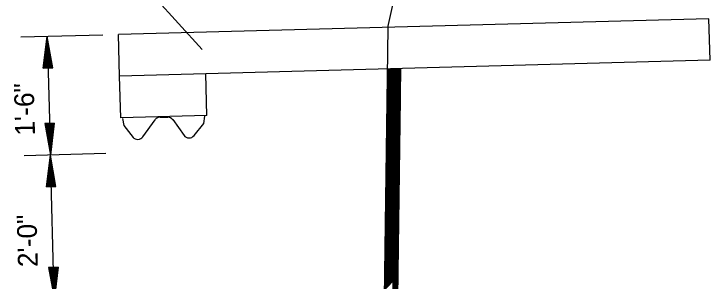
# Model space of a CAD drawing. Extents: x 1929624 to 1936506, y 596315 to 605721.
# Drawn here: x 1932251.9 to 1932463, y 600610.8 to 600691.9 of the extents above; entities that cross this region are included whole.
import ezdxf

# ---------------------------------------------------------------- set-up
doc = ezdxf.new("R2010")
doc.units = 0
doc.layers.add('Default', color=7, linetype='Continuous')

msp = doc.modelspace()

# ---------------------------------------------------------------- linework, layer by layer
at = {"layer": 'Default'}
for p, q in [((1932365.29, 600687.8), (1932409.04, 600885.31)), ((1932308.96, 600681.05), (1932287.75, 600704.49)), ((1932365.29, 600687.8), (1932362.18, 600451.38)), ((1932278.83, 600685.48), (1932253.92, 600684.81)), ((1932260.78, 600675.39), (1932261.96, 600685.03)), ((1932261.96, 600685.03), (1932262.93, 600649.04)), ((1932263.66, 600675.47), (1932261.96, 600685.03)), ((1932283.91, 600673.01), (1932283.58, 600685.61)), ((1932261.02, 600675.4), (1932262, 600683.45)), ((1932263.42, 600675.47), (1932262, 600683.45)), ((1932261.26, 600675.41), (1932262.05, 600681.79)), ((1932263.15, 600675.46), (1932262.05, 600681.79)), ((1932261.5, 600675.41), (1932262.09, 600680.18)), ((1932261.74, 600675.42), (1932262.13, 600678.55)), ((1932262.91, 600675.45), (1932262.09, 600680.18)), ((1932262.67, 600675.45), (1932262.13, 600678.55)), ((1932261.98, 600675.43), (1932262.18, 600676.97)), ((1932262.43, 600675.44), (1932262.18, 600676.97)), ((1932463.02, 600677.82), (1932310.04, 600673.72)), ((1932260.78, 600675.39), (1932263.66, 600675.47)), ((1932365.13, 600675.19), (1932366.85, 600610.85)), ((1932365.18, 600675.2), (1932366.9, 600610.9)), ((1932365.23, 600675.2), (1932366.95, 600610.96)), ((1932365.28, 600675.2), (1932367, 600611.01)), ((1932365.33, 600675.2), (1932367.05, 600611.06)), ((1932365.38, 600675.2), (1932367.1, 600611.11)), ((1932365.43, 600675.2), (1932367.14, 600611.17)), ((1932365.48, 600675.2), (1932367.19, 600611.22)), ((1932365.53, 600675.21), (1932367.24, 600611.27)), ((1932365.58, 600675.21), (1932367.29, 600611.32)), ((1932365.63, 600675.21), (1932367.34, 600611.38)), ((1932365.68, 600675.21), (1932367.39, 600611.43)), ((1932365.73, 600675.21), (1932367.44, 600611.48)), ((1932365.78, 600675.21), (1932367.48, 600611.53)), ((1932365.83, 600675.21), (1932367.53, 600611.59)), ((1932365.88, 600675.21), (1932367.58, 600611.64)), ((1932365.93, 600675.22), (1932367.63, 600611.69)), ((1932365.98, 600675.22), (1932367.68, 600611.74)), ((1932366.03, 600675.22), (1932367.73, 600611.8)), ((1932366.08, 600675.22), (1932367.78, 600611.85)), ((1932366.13, 600675.22), (1932367.82, 600611.9)), ((1932366.18, 600675.22), (1932367.87, 600611.95)), ((1932369.13, 600675.3), (1932366.19, 600451.33)), ((1932366.23, 600675.22), (1932367.92, 600612)), ((1932366.28, 600675.23), (1932367.97, 600612.06)), ((1932366.32, 600675.23), (1932368.02, 600612.11)), ((1932366.37, 600675.23), (1932368.07, 600612.16)), ((1932366.42, 600675.23), (1932368.12, 600612.21)), ((1932366.47, 600675.23), (1932368.17, 600612.27)), ((1932366.52, 600675.23), (1932368.21, 600612.32)), ((1932366.57, 600675.23), (1932368.26, 600612.37)), ((1932366.62, 600675.23), (1932368.31, 600612.52)), ((1932366.67, 600675.24), (1932368.32, 600613.77)), ((1932366.72, 600675.24), (1932368.34, 600615.02)), ((1932366.77, 600675.24), (1932368.36, 600616.27)), ((1932366.82, 600675.24), (1932368.37, 600617.53)), ((1932366.87, 600675.24), (1932368.39, 600618.78)), ((1932366.92, 600675.24), (1932368.41, 600620.03)), ((1932366.97, 600675.24), (1932368.42, 600621.28)), ((1932367.02, 600675.25), (1932368.44, 600622.53)), ((1932367.07, 600675.25), (1932368.46, 600623.78)), ((1932367.12, 600675.25), (1932368.47, 600625.03)), ((1932367.17, 600675.25), (1932368.49, 600626.28)), ((1932367.22, 600675.25), (1932368.51, 600627.53)), ((1932367.27, 600675.25), (1932368.52, 600628.78)), ((1932367.32, 600675.25), (1932368.54, 600630.04)), ((1932367.37, 600675.25), (1932368.55, 600631.29)), ((1932367.42, 600675.26), (1932368.57, 600632.54)), ((1932367.47, 600675.26), (1932368.59, 600633.79)), ((1932367.52, 600675.26), (1932368.6, 600635.04)), ((1932367.57, 600675.26), (1932368.62, 600636.29)), ((1932367.62, 600675.26), (1932368.64, 600637.54)), ((1932367.67, 600675.26), (1932368.65, 600638.79)), ((1932367.72, 600675.26), (1932368.67, 600640.04)), ((1932367.77, 600675.27), (1932368.69, 600641.3)), ((1932367.82, 600675.27), (1932368.7, 600642.55)), ((1932367.87, 600675.27), (1932368.72, 600643.8)), ((1932367.92, 600675.27), (1932368.74, 600645.05)), ((1932367.97, 600675.27), (1932368.75, 600646.3)), ((1932368.02, 600675.27), (1932368.77, 600647.55)), ((1932368.07, 600675.27), (1932368.78, 600648.8)), ((1932368.12, 600675.27), (1932368.8, 600650.05)), ((1932368.17, 600675.28), (1932368.82, 600651.3)), ((1932368.22, 600675.28), (1932368.83, 600652.55)), ((1932368.27, 600675.28), (1932368.85, 600653.81)), ((1932368.32, 600675.28), (1932368.87, 600655.06)), ((1932368.37, 600675.28), (1932368.88, 600656.31)), ((1932368.42, 600675.28), (1932368.9, 600657.56)), ((1932368.47, 600675.28), (1932368.92, 600658.81)), ((1932368.52, 600675.29), (1932368.93, 600660.06)), ((1932368.57, 600675.29), (1932368.95, 600661.31)), ((1932368.62, 600675.29), (1932368.97, 600662.56)), ((1932368.67, 600675.29), (1932368.98, 600663.81)), ((1932368.72, 600675.29), (1932369, 600665.07)), ((1932368.77, 600675.29), (1932369.02, 600666.32)), ((1932368.82, 600675.29), (1932369.03, 600667.57)), ((1932368.87, 600675.3), (1932369.05, 600668.82)), ((1932368.92, 600675.3), (1932369.06, 600670.07)), ((1932368.97, 600675.3), (1932369.08, 600671.32)), ((1932369.02, 600675.3), (1932369.1, 600672.57)), ((1932369.07, 600675.3), (1932369.11, 600673.82)), ((1932369.12, 600675.3), (1932369.13, 600675.07)), ((1932310.04, 600673.72), (1932283.91, 600673.01)), ((1932284.25, 600660.37), (1932283.91, 600673.01)), ((1932310.38, 600661.07), (1932310.04, 600673.72)), ((1932365.09, 600672.7), (1932366.76, 600610.75)), ((1932365.11, 600673.96), (1932366.8, 600610.8)), ((1932365.06, 600670.2), (1932366.66, 600610.64)), ((1932365.08, 600671.45), (1932366.71, 600610.69)), ((1932365.04, 600668.95), (1932366.61, 600610.59)), ((1932365.01, 600666.45), (1932366.51, 600610.49)), ((1932365.03, 600667.7), (1932366.56, 600610.54)), ((1932364.98, 600663.95), (1932366.42, 600610.38)), ((1932364.99, 600665.2), (1932366.46, 600610.43)), ((1932364.96, 600662.7), (1932366.37, 600610.33)), ((1932310.38, 600661.07), (1932284.25, 600660.37)), ((1932284.83, 600660.17), (1932285.16, 600657.99)), ((1932290.96, 600654.57), (1932294.74, 600659.76)), ((1932296.2, 600660.57), (1932298.56, 600660.54)), ((1932300.02, 600659.81), (1932303.46, 600655)), ((1932309.44, 600658.65), (1932309.79, 600660.82)), ((1932364.93, 600660.19), (1932366.27, 600610.22)), ((1932364.94, 600661.45), (1932366.32, 600610.28)), ((1932264.11, 600658.68), (1932261.23, 600658.6)), ((1932261.23, 600658.6), (1932262.93, 600649.04)), ((1932261.47, 600658.61), (1932262.88, 600650.65)), ((1932261.71, 600658.61), (1932262.84, 600652.31)), ((1932261.95, 600658.62), (1932262.8, 600653.89)), ((1932262.19, 600658.63), (1932262.75, 600655.52)), ((1932262.43, 600658.63), (1932262.71, 600657.13)), ((1932262.88, 600658.64), (1932262.71, 600657.13)), ((1932263.12, 600658.65), (1932262.75, 600655.52)), ((1932263.36, 600658.66), (1932262.8, 600653.89)), ((1932263.6, 600658.66), (1932262.84, 600652.31)), ((1932263.87, 600658.67), (1932262.88, 600650.65)), ((1932264.11, 600658.68), (1932262.93, 600649.04)), ((1932285.16, 600657.99), (1932288.04, 600654.4)), ((1932306.49, 600654.94), (1932309.44, 600658.65)), ((1932364.9, 600657.69), (1932366.17, 600610.12)), ((1932364.91, 600658.94), (1932366.22, 600610.17)), ((1932364.86, 600655.19), (1932366.07, 600610.01)), ((1932364.88, 600656.44), (1932366.12, 600610.07)), ((1932364.85, 600653.94), (1932366.03, 600609.96)), ((1932364.81, 600651.44), (1932365.93, 600609.86)), ((1932364.83, 600652.69), (1932365.98, 600609.91)), ((1932279.79, 600649.5), (1932255.01, 600648.83)), ((1932261.74, 600639.41), (1932262.93, 600649.04)), ((1932264.1, 600605.33), (1932262.93, 600649.04)), ((1932264.62, 600639.48), (1932262.93, 600649.04)), ((1932364.78, 600648.93), (1932365.83, 600609.75)), ((1932364.8, 600650.19), (1932365.88, 600609.8)), ((1932261.98, 600639.41), (1932262.97, 600647.44)), ((1932264.38, 600639.48), (1932262.97, 600647.44)), ((1932364.76, 600647.68), (1932365.78, 600609.7)), ((1932262.22, 600639.42), (1932263.01, 600645.78)), ((1932264.14, 600639.47), (1932263.01, 600645.78)), ((1932364.73, 600645.18), (1932365.69, 600609.59)), ((1932364.75, 600646.43), (1932365.73, 600609.65)), ((1932262.46, 600639.43), (1932263.06, 600644.2)), ((1932262.73, 600639.43), (1932263.1, 600642.56)), ((1932263.9, 600639.47), (1932263.06, 600644.2)), ((1932263.66, 600639.46), (1932263.1, 600642.56)), ((1932364.7, 600642.68), (1932365.59, 600609.49)), ((1932364.71, 600643.93), (1932365.64, 600609.54)), ((1932262.97, 600639.44), (1932263.14, 600640.96)), ((1932263.4, 600639.45), (1932263.14, 600640.96)), ((1932364.68, 600641.43), (1932365.54, 600609.44)), ((1932261.74, 600639.41), (1932264.62, 600639.48)), ((1932364.65, 600638.93), (1932365.44, 600609.33)), ((1932364.66, 600640.18), (1932365.49, 600609.39)), ((1932364.62, 600636.42), (1932365.35, 600609.23)), ((1932364.63, 600637.68), (1932365.39, 600609.28)), ((1932364.6, 600635.17), (1932365.3, 600609.18)), ((1932364.57, 600632.67), (1932365.2, 600609.07)), ((1932364.58, 600633.92), (1932365.25, 600609.12)), ((1932364.53, 600630.17), (1932365.1, 600608.97)), ((1932364.55, 600631.42), (1932365.15, 600609.02)), ((1932364.52, 600628.92), (1932365.05, 600608.91)), ((1932364.48, 600626.42), (1932364.96, 600608.81)), ((1932364.5, 600627.67), (1932365.01, 600608.86)), ((1932364.45, 600623.91), (1932364.86, 600608.7)), ((1932364.47, 600625.16), (1932364.91, 600608.76)), ((1932364.42, 600621.41), (1932364.76, 600608.6)), ((1932364.43, 600622.66), (1932364.81, 600608.65)), ((1932364.4, 600620.16), (1932364.71, 600608.55)), ((1932364.37, 600617.66), (1932364.62, 600608.44)), ((1932364.39, 600618.91), (1932364.67, 600608.49)), ((1932364.34, 600615.16), (1932364.52, 600608.34)), ((1932364.35, 600616.41), (1932364.57, 600608.39)), ((1932265.28, 600614.97), (1932262.4, 600614.89)), ((1932262.4, 600614.89), (1932264.1, 600605.33)), ((1932262.64, 600614.89), (1932264.06, 600606.94)), ((1932262.88, 600614.9), (1932264.01, 600608.59)), ((1932263.12, 600614.91), (1932263.97, 600610.18)), ((1932263.36, 600614.91), (1932263.93, 600611.81)), ((1932263.63, 600614.92), (1932263.88, 600613.42)), ((1932264.06, 600614.93), (1932263.88, 600613.42)), ((1932264.3, 600614.94), (1932263.93, 600611.81)), ((1932264.56, 600614.95), (1932263.97, 600610.18)), ((1932264.8, 600614.95), (1932264.01, 600608.59)), ((1932265.04, 600614.96), (1932264.06, 600606.94)), ((1932265.28, 600614.97), (1932264.1, 600605.33)), ((1932364.32, 600613.91), (1932364.47, 600608.28)), ((1932364.29, 600611.4), (1932364.37, 600608.18)), ((1932364.3, 600612.65), (1932364.42, 600608.23)), ((1932367.84, 600576.83), (1932366.93, 600610.85)), ((1932367.85, 600577.43), (1932366.95, 600610.88)), ((1932367.86, 600578.03), (1932366.97, 600610.9)), ((1932367.86, 600578.63), (1932367, 600610.92)), ((1932367.87, 600579.23), (1932367.02, 600610.95)), ((1932367.88, 600579.83), (1932367.04, 600610.97)), ((1932367.89, 600580.43), (1932367.07, 600611)), ((1932367.89, 600581.03), (1932367.09, 600611.02)), ((1932367.9, 600581.64), (1932367.11, 600611.05)), ((1932367.91, 600582.24), (1932367.14, 600611.07)), ((1932367.92, 600582.84), (1932367.16, 600611.1)), ((1932367.93, 600583.44), (1932367.18, 600611.12)), ((1932367.93, 600584.04), (1932367.21, 600611.15)), ((1932367.94, 600584.64), (1932367.23, 600611.17)), ((1932367.95, 600585.24), (1932367.25, 600611.2)), ((1932367.96, 600585.84), (1932367.28, 600611.22)), ((1932367.97, 600586.44), (1932367.3, 600611.24)), ((1932367.97, 600587.04), (1932367.32, 600611.27)), ((1932367.98, 600587.64), (1932367.35, 600611.29)), ((1932367.99, 600588.24), (1932367.37, 600611.32)), ((1932368, 600588.84), (1932367.39, 600611.34)), ((1932368.01, 600589.44), (1932367.42, 600611.37)), ((1932368.01, 600590.04), (1932367.44, 600611.39)), ((1932368.02, 600590.64), (1932367.46, 600611.42)), ((1932368.03, 600591.24), (1932367.49, 600611.44)), ((1932368.04, 600591.84), (1932367.51, 600611.47)), ((1932368.04, 600592.45), (1932367.53, 600611.49)), ((1932368.05, 600593.05), (1932367.56, 600611.52)), ((1932368.06, 600593.65), (1932367.58, 600611.54)), ((1932368.07, 600594.25), (1932367.6, 600611.56)), ((1932368.08, 600594.85), (1932367.63, 600611.59)), ((1932368.08, 600595.45), (1932367.65, 600611.61)), ((1932368.09, 600596.05), (1932367.67, 600611.64)), ((1932368.1, 600596.65), (1932367.7, 600611.66)), ((1932368.11, 600597.25), (1932367.72, 600611.69)), ((1932368.12, 600597.85), (1932367.74, 600611.71)), ((1932368.12, 600598.45), (1932367.77, 600611.74)), ((1932368.13, 600599.05), (1932367.79, 600611.76)), ((1932368.14, 600599.65), (1932367.81, 600611.79)), ((1932368.15, 600600.25), (1932367.84, 600611.81)), ((1932368.16, 600600.85), (1932367.86, 600611.84)), ((1932368.16, 600601.45), (1932367.88, 600611.86)), ((1932368.17, 600602.05), (1932367.91, 600611.89)), ((1932368.18, 600602.65), (1932367.93, 600611.91)), ((1932368.19, 600603.25), (1932367.95, 600611.93)), ((1932368.19, 600603.85), (1932367.98, 600611.96)), ((1932368.2, 600604.45), (1932368, 600611.98)), ((1932368.21, 600605.05), (1932368.02, 600612.01)), ((1932368.22, 600605.65), (1932368.05, 600612.03)), ((1932368.23, 600606.26), (1932368.07, 600612.06)), ((1932368.23, 600606.86), (1932368.09, 600612.08)), ((1932368.24, 600607.46), (1932368.12, 600612.11)), ((1932368.25, 600608.06), (1932368.14, 600612.13)), ((1932368.26, 600608.66), (1932368.16, 600612.16)), ((1932368.27, 600609.26), (1932368.19, 600612.18)), ((1932368.27, 600609.86), (1932368.21, 600612.21)), ((1932368.28, 600610.46), (1932368.23, 600612.23)), ((1932368.29, 600611.06), (1932368.26, 600612.25)), ((1932368.3, 600611.66), (1932368.28, 600612.28)), ((1932368.3, 600612.26), (1932368.3, 600612.3)), ((1932367.82, 600575.63), (1932366.88, 600610.8)), ((1932367.83, 600576.23), (1932366.9, 600610.83))]:
    msp.add_line(p, q, dxfattribs=at)
msp.add_lwpolyline([(1932463.02, 600677.82), (1932462.68, 600690.42), (1932283.58, 600685.61)], dxfattribs=at)
for centre, start, end in [((1932296.28, 600658.67), 89.1517, 143.9947), ((1932298.52, 600658.64), 35.653, 89.1961), ((1932289.43, 600655.7), 218.6962, 323.9765), ((1932305, 600656.12), 215.6908, 321.5912)]:
    msp.add_arc(centre, 1.9, start, end, dxfattribs=at)

# ---------------------------------------------------------------- texts
for s, p in [('1\'-6"', (1932258.28, 600655)), ('2\'-0"', (1932259.13, 600615.12))]:
    msp.add_text(s, height=6, rotation=91.5377, dxfattribs=at).set_placement(p)

doc.saveas('drawing.dxf')
